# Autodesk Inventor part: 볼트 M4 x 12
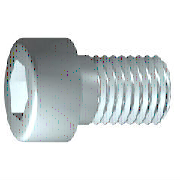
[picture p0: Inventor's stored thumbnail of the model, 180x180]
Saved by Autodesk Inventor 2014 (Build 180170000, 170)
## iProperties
IsCustomPart: 1
Created: 2012-02
Part Number: 볼트 M4 x 12
Material: 스테인리스강
Description: 6각 소켓 머리 캡 나사
Document SubType Name: Modeling
Standard: ISO 4762
Designer: mduedu
Standard Revision: Fourth edition 2004-03-01
Standards Organization: ISO
Language: ko-KR
Size Designation: M4 x 12
Categories: <MemberInstance><Categories><Category DisplayName="조임쇠" InternalName="e4da775c-781d-43d5-af7c-5136215cf5a6" Mnemonic="FSTN"><Category DisplayName="볼트" InternalN
Density: 8.08 g/cm^3
Appearance: 반광택
Mass: 2.2972 g
Surface Area: 3.30853 cm^2
Volume: 0.284306 cm^3
Author: mduedu
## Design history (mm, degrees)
sketch "스케치1"
  geometry: L1 (-1, 0)-(12, 0); L2 (12, 0)-(12, 2); L3 (12, 2)-(1.75, 2); L4 (1.75, 2)-(1.32, 2); L5 (1.32, 2)-(0, 2); L6 (0, 2)-(0, 3.5); L7 (0, 3.5)-(-4, 3.5); L8 (-4, 3.5)-(-4, 1.732); L9 (-4, 1.732)-(-2, 1.732); L10 (-2, 1.732)-(-1, 0); L11 (-7.2, 0)-(15.2, 0) reference; L12 (0, -0.7)-(0, 4.2) reference; L13 (1.75, 2)-(0, 2)
  constraints: 22 end point, 6 parallel, 2 collinear, 2 perpendicular, 1 horizontal, 1 point on line
  dimensions: "d1" = 10.25 distance from line of L3.end L2 (= GEL); "d2" = 0.42952 distance of L4.end L3.end (computed from GAL); "d3" = 4 distance between parallel lines of L8 L6 (= KOH); "d4" = 2 distance of L8.end L9.end (= INTI); "d5" = 60 deg angle of L10 L1; "d6" = 4 diameter of L3 L1 (= GD); "d7" = 4 diameter of L5 L1 (= BDM); "d8" = 3.4641 diameter of L9 L1 (= 1.1547 x SW); "d9" = 7 diameter of L7 L1 (= KOD); "d26" = 12 distance between parallel lines of L12 L2 (= NLG)
revolve "본체" sketch "스케치1" stored, may be unused: angle "d10" = 90 deg
sketch "스케치2"
  geometry: L1 (0, -4.9)-(0, 4.9) reference; L2 (-4.9, 0)-(4.9, 0) reference; L3 (1.732, 0)-(0.866, -1.5); L4 (0.866, -1.5)-(-0.866, -1.5); L5 (-0.866, -1.5)-(-1.732, 0); L6 (-1.732, 0)-(-0.866, 1.5); L7 (-0.866, 1.5)-(0.866, 1.5); L8 (0.866, 1.5)-(1.732, 0); 2 further points
  constraints: 12 end point, 1 coincident, 1 horizontal alignment, 1 point on line, 12 other
extrude "슬롯" join sketch "스케치2" stored distance "d11" = 10; taper "d12" = 0 deg
workplane "Work Plane1"
fillet "Fillet2" dims "d30" = 0.1 (= R)
body "Solid1"
fillet "모깎기1" dims "d17" = 0.4 (= RR)
feature "스레드" dims "d13" = 10.25 (= GEL), "d14" = 0
chamfer "모따기1" distance "d15" = 0.42941 (= -0.5 x SPD + 0.5 x GD); stored, may be unused: second distance "d16" = 0.42941 (= GUL), angle "d27" = 45 deg
other parameters: "GD" = 4 [user parameter; used in 2 equation terms], "NLG" = 12 [user parameter; used in 1 equation term], "GEL" = 10.25 [user parameter; used in 2 equation terms], "KOD" = 7 [user parameter; used in 1 equation term], "KOH" = 4 [user parameter; used in 1 equation term], "INTI" = 2 [user parameter; used in 1 equation term], "GAL" = 0.42941 (= 0.61345 x PTC) [user parameter; used in 1 equation term], "GUL" = 0.42941 (= 0.61345 x PTC) [user parameter; used in 1 equation term], "BDM" = 4 (= NND) [user parameter; used in 1 equation term], "SW" = 3 [user parameter; used in 2 equation terms], "RR" = 0.4 [user parameter; used in 1 equation term], "SPD" = 3.14117 (= NND - 1.2269 x PTC) [user parameter; used in 1 equation term], "d19" = 0, "d28" = 0, "d29" = 0, "R" = 0.1 [user parameter; used in 1 equation term], "TOA" = 30 deg [user parameter], "GD1" = 3.14117 (= THREADDIA - 1.2269 x PTC) [user parameter], "THREADDIA" = 4 [user parameter; used in 1 equation term], "FAWI" = 45 deg [user parameter], "TPU" = 14.28571 (computed from PTC) [user parameter], "PTC" = 0.7 [user parameter; used in 5 equation terms], "NND" = 4 [user parameter; used in 2 equation terms], "E0" = 3.465 (= 1.155 x SW) [user parameter]
